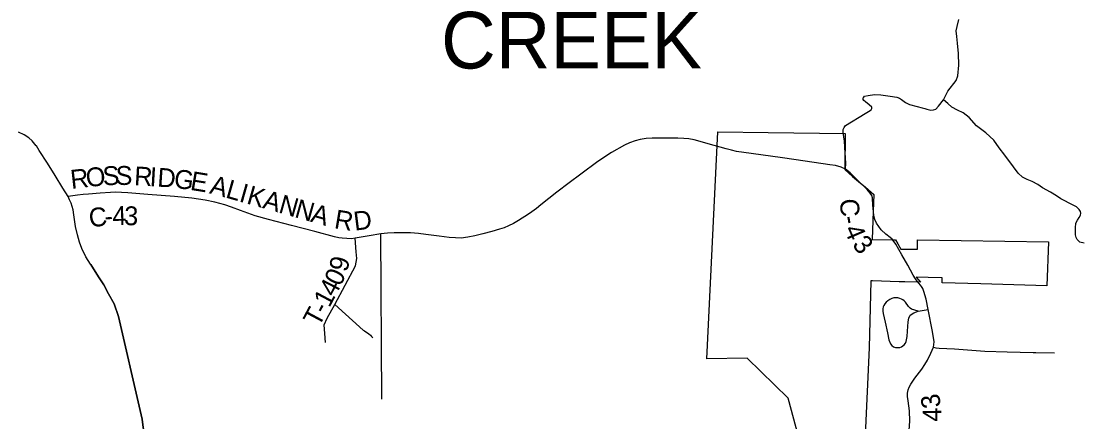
# Model space of a CAD drawing. Extents: x 2402298 to 2498138, y 789485 to 950881.
# Drawn here: x 2459820 to 2476688, y 877630 to 883995 of the extents above; entities that cross this region are included whole.
import ezdxf

# ---------------------------------------------------------------- set-up
doc = ezdxf.new("R2010")
doc.units = 0
for name, color, linetype in [('GM_X_Corporation', 7, 'Continuous'), ('GM_X_County_Road_Text', 7, 'Continuous'), ('GM_X_State_Route', 7, 'Continuous'), ('GM_X_Township_Road', 7, 'Continuous'), ('GM_X_Township_Road_Text', 7, 'Continuous'), ('GM_X_Township_Text', 7, 'Continuous'), ('SC_Scratch1', 7, 'Continuous'), ('SH_Text', 7, 'Continuous')]:
    doc.layers.add(name, color=color, linetype=linetype)

msp = doc.modelspace()

# ---------------------------------------------------------------- linework, layer by layer
at = {"layer": 'GM_X_Corporation'}
msp.add_lwpolyline([(2472334, 876785), (2472008, 878006), (2471357, 878639), (2470714, 878629), (2470890, 882238), (2471689, 882227), (2472915, 882209), (2472907, 881637), (2473031, 881530), (2473126, 881449), (2473156, 881423), (2473204, 881382), (2473234, 881356), (2473368, 881242), (2473358, 880979), (2473342, 880524), (2473663, 880520), (2473713, 880520), (2473748, 880456), (2473796, 880375), (2474061, 880375), (2474061, 880519), (2476146, 880490), (2476116, 879790), (2475070, 879823), (2474453, 879839), (2474452, 879919), (2474231, 879924), (2474041, 879930), (2474107, 879846), (2473861, 879851), (2473773, 879853), (2473345, 879868), (2473322, 879868), (2473296, 878806), (2473230, 877418)], dxfattribs=at)
at = {"layer": 'GM_X_State_Route'}
for points in [[(2460061, 882013), (2460058, 882017), (2459994, 882093), (2459939, 882144), (2459867, 882190), (2459777, 882234)], [(2460922, 880134), (2460847, 880253), (2460785, 880382), (2460747, 880483), (2460712, 880603), (2460684, 880733), (2460656, 880919), (2460644, 880997), (2460614, 881102), (2460587, 881156), (2460564, 881208), (2460480, 881340), (2460358, 881541), (2460237, 881739), (2460107, 881943), (2460061, 882013)], [(2461769, 877479), (2461759, 877537), (2461740, 877673), (2461709, 877810), (2461365, 879301), (2461296, 879505), (2461209, 879664), (2461130, 879804), (2461047, 879934), (2460924, 880129), (2460922, 880134)]]:
    msp.add_lwpolyline(points, dxfattribs=at)
at = {"layer": 'GM_X_Township_Road'}
for p, q in [((2465551, 877988), (2465536, 880618)), ((2475944, 878729), (2476238, 878724))]:
    msp.add_line(p, q, dxfattribs=at)
for points in [[(2474179, 882607), (2474209, 882598), (2474275, 882584), (2474318, 882587), (2474351, 882600), (2474397, 882643), (2474475, 882745), (2474545, 882882), (2474675, 883053), (2474704, 883129), (2474720, 883297), (2474714, 883481), (2474696, 883647), (2474685, 883751), (2474678, 883840), (2474694, 883910), (2474720, 884023)], [(2472882, 882226), (2472879, 882247), (2472880, 882277), (2472894, 882306), (2472918, 882336), (2473231, 882527), (2473285, 882559), (2473326, 882587), (2473338, 882609), (2473335, 882630), (2473295, 882665), (2473234, 882716), (2473211, 882735), (2473201, 882749), (2473198, 882762), (2473200, 882776), (2473208, 882790), (2473222, 882803), (2473277, 882816), (2473379, 882829), (2473477, 882825), (2473630, 882805), (2473732, 882786), (2473778, 882770), (2473806, 882752), (2473873, 882706), (2473936, 882672), (2474057, 882638), (2474134, 882620), (2474179, 882607)], [(2476712, 880467), (2476643, 880486), (2476618, 880504), (2476601, 880524), (2476582, 880560), (2476571, 880600), (2476572, 880713), (2476580, 880787), (2476602, 880836), (2476632, 880878), (2476650, 880912), (2476658, 880944), (2476654, 880971), (2476632, 881005), (2476587, 881043), (2476534, 881072), (2476339, 881173), (2476270, 881222), (2476174, 881280), (2476047, 881350), (2475973, 881401), (2475885, 881449), (2475803, 881482), (2475763, 881499), (2475729, 881518), (2475662, 881578), (2475585, 881679), (2475448, 881869), (2475357, 881984), (2475275, 882103), (2475145, 882221), (2474997, 882334), (2474882, 882466), (2474786, 882541), (2474695, 882584), (2474609, 882631), (2474543, 882689), (2474475, 882745)], [(2472920, 881646), (2472921, 881741), (2472912, 881902), (2472902, 882090), (2472882, 882226)], [(2464657, 878887), (2464644, 879035), (2464636, 879171), (2464681, 879274), (2464801, 879492), (2465130, 880109), (2465154, 880225), (2465142, 880332), (2465128, 880545)], [(2474071, 879387), (2473969, 879419), (2473943, 879437), (2473918, 879461), (2473870, 879528), (2473849, 879549), (2473830, 879565), (2473807, 879580), (2473783, 879591), (2473750, 879598), (2473719, 879600), (2473688, 879599), (2473656, 879590), (2473621, 879575), (2473589, 879554), (2473563, 879533), (2473541, 879506), (2473527, 879480), (2473517, 879454), (2473511, 879423), (2473511, 879388), (2473516, 879348), (2473547, 879211), (2473583, 879042), (2473607, 878932), (2473634, 878866), (2473652, 878842), (2473678, 878822), (2473710, 878812), (2473749, 878809), (2473781, 878811), (2473807, 878820), (2473830, 878834), (2473850, 878853), (2473869, 878877), (2473881, 878905), (2473895, 878984), (2473904, 879069), (2473914, 879217), (2473922, 879278), (2473944, 879323), (2474001, 879362), (2474071, 879387), (2474233, 879412)], [(2464801, 879492), (2465253, 879087), (2465274, 879076), (2465298, 879061), (2465322, 879045), (2465345, 879026), (2465368, 879005), (2465387, 878985), (2465405, 878964)], [(2474316, 878815), (2474354, 878806), (2474407, 878801), (2474648, 878789), (2475131, 878753), (2475485, 878743), (2475900, 878729), (2475944, 878729)]]:
    msp.add_lwpolyline(points, dxfattribs=at)
at = {"layer": 'SC_Scratch1'}
for p, q in [((2469486, 882065), (2469405, 882026)), ((2469575, 882095), (2469486, 882065)), ((2469657, 882116), (2469575, 882095)), ((2469751, 882130), (2469657, 882116)), ((2469844, 882136), (2469751, 882130)), ((2470058, 882139), (2469844, 882136)), ((2470254, 882136), (2470058, 882139)), ((2470349, 882133), (2470254, 882136)), ((2470426, 882125), (2470349, 882133)), ((2470513, 882109), (2470426, 882125)), ((2470682, 882064), (2470513, 882109)), ((2470738, 882048), (2470682, 882064)), ((2471020, 881968), (2470738, 882048)), ((2469197, 881907), (2468982, 881766)), ((2469405, 882026), (2469197, 881907)), ((2471105, 881945), (2471020, 881968)), ((2471186, 881927), (2471105, 881945)), ((2471419, 881893), (2471186, 881927)), ((2471919, 881825), (2471419, 881893)), ((2468982, 881766), (2468711, 881567)), ((2472276, 881771), (2471919, 881825)), ((2472667, 881715), (2472276, 881771)), ((2472757, 881700), (2472667, 881715)), ((2472851, 881678), (2472757, 881700)), ((2468711, 881567), (2468525, 881427)), ((2472920, 881646), (2472851, 881678)), ((2472992, 881585), (2472920, 881646)), ((2473113, 881462), (2472992, 881585)), ((2468525, 881427), (2468333, 881280)), ((2473260, 881322), (2473113, 881462)), ((2460715, 881231), (2460564, 881208)), ((2460806, 881242), (2460715, 881231)), ((2460887, 881246), (2460806, 881242)), ((2461072, 881261), (2460887, 881246)), ((2461240, 881275), (2461072, 881261)), ((2461314, 881279), (2461240, 881275)), ((2461516, 881268), (2461314, 881279)), ((2461832, 881243), (2461516, 881268)), ((2462256, 881212), (2461832, 881243)), ((2462531, 881184), (2462256, 881212)), ((2468333, 881280), (2468076, 881077)), ((2473312, 881260), (2473260, 881322)), ((2473336, 881226), (2473312, 881260)), ((2473347, 881190), (2473336, 881226)), ((2462745, 881151), (2462531, 881184)), ((2462897, 881120), (2462745, 881151)), ((2463056, 881078), (2462897, 881120)), ((2463163, 881042), (2463056, 881078)), ((2463303, 880989), (2463163, 881042)), ((2468076, 881077), (2468005, 881019)), ((2473349, 881184), (2473347, 881190)), ((2473353, 881072), (2473349, 881184)), ((2473360, 880972), (2473353, 881072)), ((2463535, 880905), (2463303, 880989)), ((2463747, 880846), (2463535, 880905)), ((2467782, 880865), (2467722, 880827)), ((2467866, 880919), (2467782, 880865)), ((2467932, 880967), (2467866, 880919)), ((2468005, 881019), (2467932, 880967)), ((2473370, 880901), (2473360, 880972)), ((2473385, 880845), (2473370, 880901)), ((2464116, 880751), (2463747, 880846)), ((2464487, 880655), (2464116, 880751)), ((2467420, 880691), (2467296, 880655)), ((2467492, 880714), (2467420, 880691)), ((2467561, 880742), (2467492, 880714)), ((2467643, 880783), (2467561, 880742)), ((2467722, 880827), (2467643, 880783)), ((2473409, 880784), (2473385, 880845)), ((2473483, 880682), (2473409, 880784)), ((2464798, 880571), (2464487, 880655)), ((2464865, 880555), (2464798, 880571)), ((2464919, 880548), (2464865, 880555)), ((2464995, 880541), (2464919, 880548)), ((2465067, 880538), (2464995, 880541)), ((2465128, 880545), (2465067, 880538)), ((2465346, 880586), (2465128, 880545)), ((2465536, 880618), (2465346, 880586)), ((2465639, 880629), (2465536, 880618)), ((2465746, 880633), (2465639, 880629)), ((2465864, 880633), (2465746, 880633)), ((2466005, 880630), (2465864, 880633)), ((2466130, 880620), (2466005, 880630)), ((2466248, 880606), (2466130, 880620)), ((2466459, 880578), (2466248, 880606)), ((2466620, 880560), (2466459, 880578)), ((2466719, 880552), (2466620, 880560)), ((2466810, 880550), (2466719, 880552)), ((2466917, 880561), (2466810, 880550)), ((2467030, 880585), (2466917, 880561)), ((2467154, 880615), (2467030, 880585)), ((2467296, 880655), (2467154, 880615)), ((2473557, 880613), (2473483, 880682)), ((2473630, 880556), (2473557, 880613)), ((2473660, 880532), (2473630, 880556)), ((2473716, 880451), (2473660, 880532)), ((2473814, 880284), (2473716, 880451)), ((2473909, 880117), (2473814, 880284)), ((2473994, 879960), (2473909, 880117)), ((2474029, 879899), (2473994, 879960)), ((2474038, 879887), (2474029, 879899)), ((2474083, 879832), (2474038, 879887)), ((2474111, 879801), (2474083, 879832)), ((2474126, 879779), (2474111, 879801)), ((2474144, 879749), (2474126, 879779)), ((2474164, 879701), (2474144, 879749)), ((2474201, 879577), (2474164, 879701)), ((2474233, 879412), (2474201, 879577)), ((2474298, 879066), (2474233, 879412)), ((2474325, 878901), (2474298, 879066)), ((2474316, 878815), (2474325, 878901)), ((2474219, 878608), (2474275, 878719)), ((2474275, 878719), (2474316, 878815)), ((2474128, 878463), (2474180, 878539)), ((2474180, 878539), (2474219, 878608)), ((2474022, 878323), (2474128, 878463)), ((2473913, 878138), (2473931, 878181)), ((2473931, 878181), (2473955, 878227)), ((2473955, 878227), (2474022, 878323)), ((2473902, 878085), (2473913, 878138)), ((2473902, 878030), (2473902, 878085)), ((2473911, 877964), (2473902, 878030)), ((2473937, 877804), (2473911, 877964)), ((2473940, 877640), (2473937, 877804)), ((2473923, 877422), (2473940, 877640))]:
    msp.add_line(p, q, dxfattribs=at)
at = {"layer": 'SH_Text'}
for p, q in [((2469486, 882065), (2469405, 882026)), ((2469575, 882095), (2469486, 882065)), ((2469657, 882116), (2469575, 882095)), ((2469751, 882130), (2469657, 882116)), ((2469844, 882136), (2469751, 882130)), ((2470058, 882139), (2469844, 882136)), ((2470254, 882136), (2470058, 882139)), ((2470349, 882133), (2470254, 882136)), ((2470426, 882125), (2470349, 882133)), ((2470513, 882109), (2470426, 882125)), ((2470682, 882064), (2470513, 882109)), ((2470738, 882048), (2470682, 882064)), ((2471020, 881968), (2470738, 882048)), ((2469197, 881907), (2468982, 881766)), ((2469405, 882026), (2469197, 881907)), ((2471105, 881945), (2471020, 881968)), ((2471186, 881927), (2471105, 881945)), ((2471419, 881893), (2471186, 881927)), ((2471919, 881825), (2471419, 881893)), ((2468982, 881766), (2468711, 881567)), ((2472276, 881771), (2471919, 881825)), ((2472667, 881715), (2472276, 881771)), ((2472757, 881700), (2472667, 881715)), ((2472851, 881678), (2472757, 881700)), ((2468711, 881567), (2468525, 881427)), ((2472920, 881646), (2472851, 881678)), ((2472992, 881585), (2472920, 881646)), ((2473113, 881462), (2472992, 881585)), ((2468525, 881427), (2468333, 881280)), ((2473260, 881322), (2473113, 881462)), ((2460715, 881231), (2460564, 881208)), ((2460587, 881156), (2460564, 881208)), ((2460806, 881242), (2460715, 881231)), ((2460887, 881246), (2460806, 881242)), ((2461072, 881261), (2460887, 881246)), ((2461240, 881275), (2461072, 881261)), ((2461314, 881279), (2461240, 881275)), ((2461516, 881268), (2461314, 881279)), ((2461832, 881243), (2461516, 881268)), ((2462256, 881212), (2461832, 881243)), ((2462531, 881184), (2462256, 881212)), ((2468333, 881280), (2468076, 881077)), ((2473312, 881260), (2473260, 881322)), ((2473336, 881226), (2473312, 881260)), ((2473347, 881190), (2473336, 881226)), ((2460614, 881102), (2460587, 881156)), ((2460644, 880997), (2460614, 881102)), ((2462745, 881151), (2462531, 881184)), ((2462897, 881120), (2462745, 881151)), ((2463056, 881078), (2462897, 881120)), ((2463163, 881042), (2463056, 881078)), ((2463303, 880989), (2463163, 881042)), ((2468076, 881077), (2468005, 881019)), ((2473349, 881184), (2473347, 881190)), ((2473353, 881072), (2473349, 881184)), ((2473360, 880972), (2473353, 881072)), ((2460656, 880919), (2460644, 880997)), ((2460684, 880733), (2460656, 880919)), ((2463535, 880905), (2463303, 880989)), ((2463747, 880846), (2463535, 880905)), ((2467782, 880865), (2467722, 880827)), ((2467866, 880919), (2467782, 880865)), ((2467932, 880967), (2467866, 880919)), ((2468005, 881019), (2467932, 880967)), ((2473370, 880901), (2473360, 880972)), ((2473385, 880845), (2473370, 880901)), ((2460712, 880603), (2460684, 880733)), ((2464116, 880751), (2463747, 880846)), ((2464487, 880655), (2464116, 880751)), ((2467420, 880691), (2467296, 880655)), ((2467492, 880714), (2467420, 880691)), ((2467561, 880742), (2467492, 880714)), ((2467643, 880783), (2467561, 880742)), ((2467722, 880827), (2467643, 880783)), ((2473409, 880784), (2473385, 880845)), ((2473483, 880682), (2473409, 880784)), ((2460747, 880483), (2460712, 880603)), ((2464798, 880571), (2464487, 880655)), ((2464865, 880555), (2464798, 880571)), ((2464919, 880548), (2464865, 880555)), ((2464995, 880541), (2464919, 880548)), ((2465067, 880538), (2464995, 880541)), ((2465128, 880545), (2465067, 880538)), ((2465346, 880586), (2465128, 880545)), ((2465536, 880618), (2465346, 880586)), ((2465639, 880629), (2465536, 880618)), ((2465746, 880633), (2465639, 880629)), ((2465864, 880633), (2465746, 880633)), ((2466005, 880630), (2465864, 880633)), ((2466130, 880620), (2466005, 880630)), ((2466248, 880606), (2466130, 880620)), ((2466459, 880578), (2466248, 880606)), ((2466620, 880560), (2466459, 880578)), ((2466719, 880552), (2466620, 880560)), ((2466810, 880550), (2466719, 880552)), ((2466917, 880561), (2466810, 880550)), ((2467030, 880585), (2466917, 880561)), ((2467154, 880615), (2467030, 880585)), ((2467296, 880655), (2467154, 880615)), ((2473557, 880613), (2473483, 880682)), ((2473630, 880556), (2473557, 880613)), ((2473660, 880532), (2473630, 880556)), ((2473716, 880451), (2473660, 880532)), ((2460785, 880382), (2460747, 880483)), ((2460847, 880253), (2460785, 880382)), ((2473814, 880284), (2473716, 880451)), ((2460922, 880134), (2460847, 880253)), ((2473909, 880117), (2473814, 880284)), ((2473994, 879960), (2473909, 880117)), ((2474029, 879899), (2473994, 879960)), ((2474038, 879887), (2474029, 879899)), ((2474083, 879832), (2474038, 879887)), ((2474111, 879801), (2474083, 879832)), ((2474126, 879779), (2474111, 879801)), ((2474144, 879749), (2474126, 879779)), ((2474164, 879701), (2474144, 879749)), ((2474201, 879577), (2474164, 879701)), ((2474233, 879412), (2474201, 879577)), ((2474298, 879066), (2474233, 879412)), ((2474325, 878901), (2474298, 879066)), ((2474316, 878815), (2474325, 878901)), ((2474219, 878608), (2474275, 878719)), ((2474275, 878719), (2474316, 878815)), ((2474128, 878463), (2474180, 878539)), ((2474180, 878539), (2474219, 878608)), ((2474022, 878323), (2474128, 878463)), ((2473913, 878138), (2473931, 878181)), ((2473931, 878181), (2473955, 878227)), ((2473955, 878227), (2474022, 878323)), ((2473902, 878085), (2473913, 878138)), ((2473902, 878030), (2473902, 878085)), ((2473911, 877964), (2473902, 878030)), ((2473937, 877804), (2473911, 877964)), ((2473940, 877640), (2473937, 877804)), ((2473923, 877422), (2473940, 877640))]:
    msp.add_line(p, q, dxfattribs=at)
msp.add_lwpolyline([(2460922, 880134), (2460924, 880129), (2461047, 879934), (2461130, 879804), (2461209, 879664), (2461296, 879505), (2461365, 879301), (2461709, 877810), (2461740, 877673), (2461759, 877537), (2461769, 877479)], dxfattribs=at)

# ---------------------------------------------------------------- texts
at = {"layer": 'GM_X_County_Road_Text'}
for s, rotation, p in [('S', 3.1804, (2461121, 881384)), ('S', 359.4346, (2461318, 881395)), ('R', 6.257, (2460617, 881330)), ('O', 6.0731, (2460862, 881357)), ('R', 356.794, (2461609, 881389)), ('I', 356.7903, (2461855, 881375)), ('D', 355.9567, (2461976, 881368)), ('G', 352.7937, (2462235, 881350)), ('E', 350.6765, (2462494, 881317)), ('A', 345.2446, (2462799, 881262)), ('L', 344.1788, (2463053, 881196)), ('I', 344.1775, (2463268, 881134)), ('K', 344.1762, (2463387, 881101)), ('A', 344.1773, (2463641, 881029)), ('N', 344.1797, (2463895, 880957)), ('C', 5.7549, (2460909, 880720)), ('4', 1.2074, (2461271, 880753)), ('3', 357.8762, (2461451, 880757)), ('N', 344.1762, (2464149, 880885)), ('A', 344.1846, (2464403, 880813)), ('C', 272.7018, (2472830, 881170)), ('-', 3.8826, (2461152, 880745)), ('R', 350.5919, (2464782, 880708)), ('D', 7.2488, (2465120, 880666)), ('-', 280.1308, (2472846, 880882)), ('4', 293.1205, (2472889, 880690)), ('3', 310.1476, (2473012, 880437)), ('3', 100.119, (2474438, 877873)), ('4', 90.1632, (2474443, 877631))]:
    msp.add_text(s, height=300, rotation=rotation, dxfattribs=at).set_placement(p)
at = {"layer": 'GM_X_Township_Road_Text'}
for s, rotation, p in [('9', 75.8528, (2464995, 879998)), ('0', 64.0846, (2464891, 879769)), ('4', 62.612, (2464803, 879598)), ('1', 62.0795, (2464715, 879432)), ('T', 61.892, (2464550, 879124)), ('-', 61.9157, (2464656, 879322))]:
    msp.add_text(s, height=300, rotation=rotation, dxfattribs=at).set_placement(p)
at = {"layer": 'GM_X_Township_Text'}
msp.add_text('CREEK', height=900, rotation=0, dxfattribs=at).set_placement((2466491, 883244))

doc.saveas('drawing.dxf')
